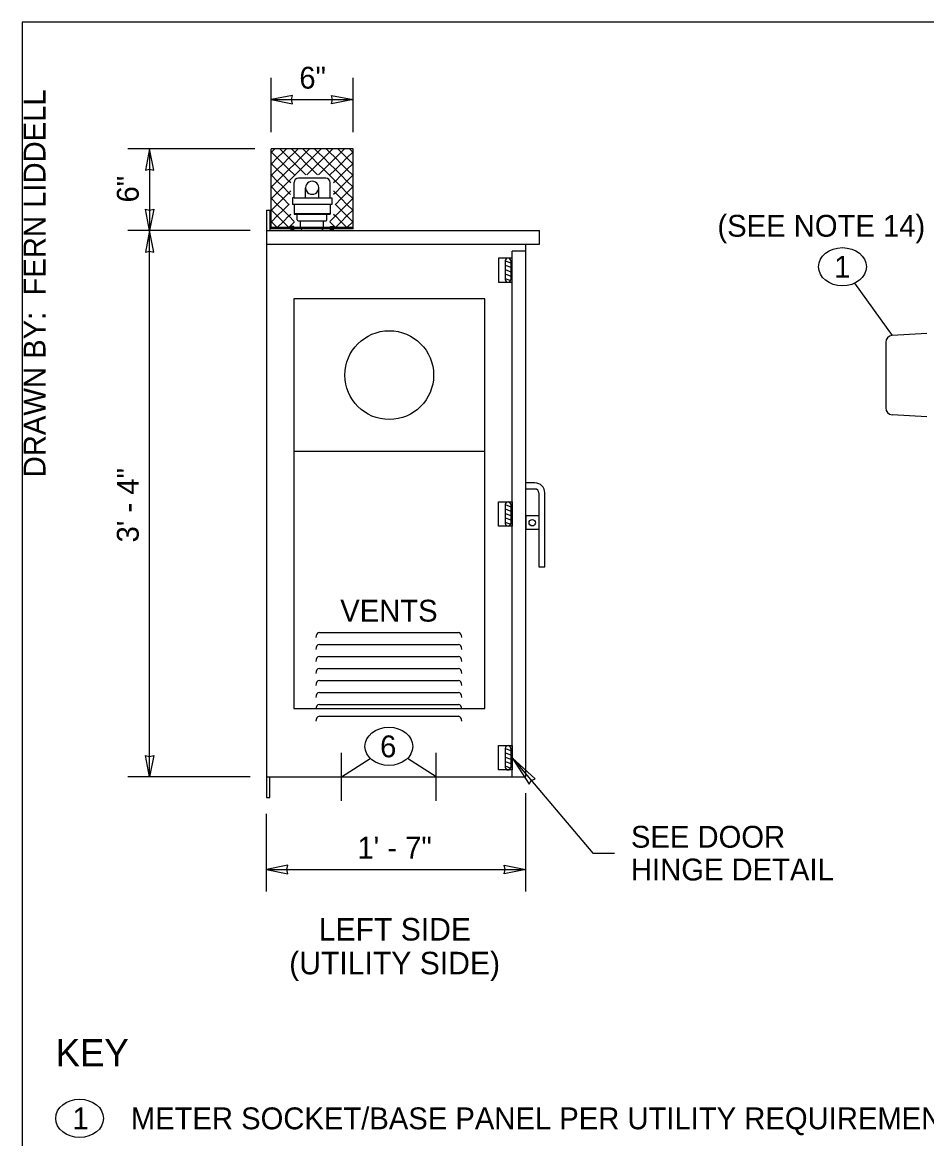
# Model space of a CAD drawing. Extents: x 99862 to 103680, y 99470 to 105076.
# Drawn here: x 99862 to 100524, y 101258 to 102076 of the extents above; entities that cross this region are included whole.
import ezdxf

# ---------------------------------------------------------------- set-up
doc = ezdxf.new("R2010")
doc.units = 0
for name, color, linetype in [('Level 1', 7, 'Continuous'), ('Level 11', 7, 'Continuous'), ('Level 15', 7, 'Continuous'), ('Level 20', 7, 'Continuous'), ('Level 3', 7, 'Continuous'), ('Level 40', 7, 'Continuous'), ('Level 62', 7, 'Continuous')]:
    doc.layers.add(name, color=color, linetype=linetype)

msp = doc.modelspace()

# ---------------------------------------------------------------- linework, layer by layer
at = {"layer": 'Level 1'}
for p, q in [((100044.28, 101925.19), (100044.28, 101982.94)), ((100104.28, 101982.94), (100044.28, 101982.94)), ((100044.28, 101980.71), (100044.5, 101980.49)), ((100044.5, 101980.49), (100044.28, 101980.27)), ((100044.5, 101980.49), (100046.95, 101982.94)), ((100048.75, 101976.24), (100044.5, 101980.49)), ((100053, 101980.49), (100048.75, 101976.24)), ((100050.55, 101982.94), (100053, 101980.49)), ((100055.46, 101982.94), (100053, 101980.49)), ((100053, 101980.49), (100057.26, 101976.24)), ((100057.26, 101976.24), (100061.51, 101980.49)), ((100061.51, 101980.49), (100059.06, 101982.94)), ((100063.97, 101982.94), (100061.51, 101980.49)), ((100061.51, 101980.49), (100065.77, 101976.24)), ((100065.77, 101976.24), (100070.02, 101980.49)), ((100070.02, 101980.49), (100067.57, 101982.94)), ((100072.47, 101982.94), (100070.02, 101980.49)), ((100070.02, 101980.49), (100074.28, 101976.24)), ((100074.28, 101976.24), (100078.53, 101980.49)), ((100078.53, 101980.49), (100076.08, 101982.94)), ((100080.98, 101982.94), (100078.53, 101980.49)), ((100078.53, 101980.49), (100082.78, 101976.24)), ((100082.78, 101976.24), (100087.04, 101980.49)), ((100087.04, 101980.49), (100084.59, 101982.94)), ((100089.49, 101982.94), (100087.04, 101980.49)), ((100087.04, 101980.49), (100091.29, 101976.24)), ((100091.29, 101976.24), (100095.55, 101980.49)), ((100093.09, 101982.94), (100095.55, 101980.49)), ((100095.55, 101980.49), (100098, 101982.94)), ((100095.55, 101980.49), (100099.8, 101976.24)), ((100099.8, 101976.24), (100104.05, 101980.49)), ((100104.05, 101980.49), (100101.6, 101982.94)), ((100104.28, 101980.71), (100104.05, 101980.49)), ((100104.05, 101980.49), (100104.28, 101980.27)), ((100104.28, 101925.19), (100104.28, 101982.95)), ((100044.28, 101972.21), (100044.5, 101971.98)), ((100044.5, 101971.98), (100044.28, 101971.76)), ((100044.5, 101971.98), (100048.75, 101976.24)), ((100048.75, 101967.73), (100044.5, 101971.98)), ((100048.75, 101976.24), (100053, 101971.98)), ((100053, 101971.98), (100048.75, 101967.73)), ((100057.26, 101976.24), (100053, 101971.98)), ((100053, 101971.98), (100057.26, 101967.73)), ((100061.51, 101971.98), (100057.26, 101976.24)), ((100057.26, 101967.73), (100061.51, 101971.98)), ((100065.77, 101976.24), (100061.51, 101971.98)), ((100061.51, 101971.98), (100065.77, 101967.73)), ((100070.02, 101971.98), (100065.77, 101976.24)), ((100065.77, 101967.73), (100070.02, 101971.98)), ((100074.28, 101976.24), (100070.02, 101971.98)), ((100070.02, 101971.98), (100074.28, 101967.73)), ((100078.53, 101971.98), (100074.28, 101976.24)), ((100074.28, 101967.73), (100078.53, 101971.98)), ((100082.78, 101976.24), (100078.53, 101971.98)), ((100078.53, 101971.98), (100082.78, 101967.73)), ((100087.04, 101971.98), (100082.78, 101976.24)), ((100082.78, 101967.73), (100087.04, 101971.98)), ((100091.29, 101976.24), (100087.04, 101971.98)), ((100087.04, 101971.98), (100091.29, 101967.73)), ((100095.55, 101971.98), (100091.29, 101976.24)), ((100091.29, 101967.73), (100095.55, 101971.98)), ((100099.8, 101976.24), (100095.55, 101971.98)), ((100095.55, 101971.98), (100099.8, 101967.73)), ((100104.05, 101971.98), (100099.8, 101976.24)), ((100099.8, 101967.73), (100104.05, 101971.98)), ((100104.28, 101972.2), (100104.05, 101971.98)), ((100104.05, 101971.98), (100104.28, 101971.76)), ((100044.28, 101963.7), (100044.5, 101963.48)), ((100044.5, 101963.48), (100044.28, 101963.25)), ((100044.5, 101963.48), (100048.75, 101967.73)), ((100048.75, 101959.22), (100044.5, 101963.48)), ((100048.75, 101967.73), (100053, 101963.48)), ((100053, 101963.48), (100048.75, 101959.22)), ((100057.26, 101967.73), (100053, 101963.48)), ((100053, 101963.48), (100057.26, 101959.22)), ((100061.51, 101963.48), (100057.26, 101967.73)), ((100057.26, 101959.22), (100061.51, 101963.48)), ((100065.77, 101967.73), (100061.51, 101963.48)), ((100061.51, 101963.48), (100061.73, 101963.26)), ((100069.64, 101963.86), (100065.77, 101967.73)), ((100074.28, 101967.73), (100070.4, 101963.86)), ((100078.15, 101963.86), (100074.28, 101967.73)), ((100082.78, 101967.73), (100078.91, 101963.86)), ((100087.04, 101963.48), (100082.78, 101967.73)), ((100086.82, 101963.26), (100087.04, 101963.48)), ((100091.29, 101967.73), (100087.04, 101963.48)), ((100087.04, 101963.48), (100091.29, 101959.22)), ((100095.55, 101963.48), (100091.29, 101967.73)), ((100091.29, 101959.22), (100095.55, 101963.48)), ((100099.8, 101967.73), (100095.55, 101963.48)), ((100095.55, 101963.48), (100099.8, 101959.22)), ((100104.05, 101963.48), (100099.8, 101967.73)), ((100099.8, 101959.22), (100104.05, 101963.48)), ((100104.28, 101963.7), (100104.05, 101963.48)), ((100104.05, 101963.48), (100104.28, 101963.26)), ((100044.28, 101955.19), (100044.5, 101954.97)), ((100044.5, 101954.97), (100044.28, 101954.75)), ((100044.5, 101954.97), (100048.75, 101959.22)), ((100048.75, 101950.71), (100044.5, 101954.97)), ((100048.75, 101959.22), (100053, 101954.97)), ((100053, 101954.97), (100048.75, 101950.71)), ((100057.26, 101959.22), (100053, 101954.97)), ((100053, 101954.97), (100057.26, 101950.71)), ((100058.63, 101957.85), (100057.26, 101959.22)), ((100061.04, 101947.01), (100061.04, 101958.24)), ((100084.3, 101961.45), (100064.25, 101961.45)), ((100069.46, 101947.01), (100069.46, 101954.39)), ((100079.09, 101947.01), (100079.09, 101954.39)), ((100087.51, 101947.01), (100087.51, 101958.24)), ((100091.29, 101959.22), (100089.92, 101957.85)), ((100095.55, 101954.97), (100091.29, 101959.22)), ((100091.29, 101950.71), (100095.55, 101954.97)), ((100099.8, 101959.22), (100095.55, 101954.97)), ((100095.55, 101954.97), (100099.8, 101950.71)), ((100104.05, 101954.97), (100099.8, 101959.22)), ((100099.8, 101950.71), (100104.05, 101954.97)), ((100104.28, 101955.19), (100104.05, 101954.97)), ((100104.05, 101954.97), (100104.28, 101954.75)), ((100044.28, 101946.68), (100044.5, 101946.46)), ((100044.5, 101946.46), (100044.28, 101946.24)), ((100044.5, 101946.46), (100048.75, 101950.71)), ((100048.75, 101942.2), (100044.5, 101946.46)), ((100048.75, 101950.71), (100053, 101946.46)), ((100053, 101946.46), (100048.75, 101942.2)), ((100057.26, 101950.71), (100053, 101946.46)), ((100053, 101946.46), (100057.26, 101942.2)), ((100057.26, 101950.71), (100058.63, 101952.09)), ((100058.56, 101949.42), (100057.26, 101950.71)), ((100061.04, 101947.01), (100059.84, 101947.01)), ((100059.84, 101947.01), (100059.84, 101942.2)), ((100061.04, 101947.01), (100087.51, 101947.01)), ((100087.51, 101947.01), (100088.71, 101947.01)), ((100088.71, 101947.01), (100088.71, 101942.2)), ((100089.92, 101952.09), (100091.29, 101950.71)), ((100091.29, 101950.71), (100090, 101949.42)), ((100095.55, 101946.46), (100091.29, 101950.71)), ((100091.29, 101942.2), (100095.55, 101946.46)), ((100099.8, 101950.71), (100095.55, 101946.46)), ((100095.55, 101946.46), (100099.8, 101942.2)), ((100104.05, 101946.46), (100099.8, 101950.71)), ((100099.8, 101942.2), (100104.05, 101946.46)), ((100104.28, 101946.68), (100104.05, 101946.46)), ((100104.05, 101946.46), (100104.28, 101946.24)), ((100044.28, 101938.17), (100044.5, 101937.95)), ((100044.5, 101937.95), (100044.28, 101937.73)), ((100044.5, 101937.95), (100048.75, 101942.2)), ((100048.75, 101933.7), (100044.5, 101937.95)), ((100048.75, 101942.2), (100053, 101937.95)), ((100053, 101937.95), (100048.75, 101933.7)), ((100057.26, 101942.2), (100053, 101937.95)), ((100053, 101937.95), (100057.26, 101933.7)), ((100057.26, 101942.2), (100057.43, 101942.38)), ((100057.43, 101942.03), (100057.26, 101942.2)), ((100088.71, 101942.2), (100059.84, 101942.2)), ((100061.04, 101942.2), (100061.04, 101934.98)), ((100087.51, 101942.2), (100087.51, 101934.98)), ((100091.12, 101942.38), (100091.29, 101942.2)), ((100091.29, 101942.2), (100091.12, 101942.03)), ((100095.55, 101937.95), (100091.29, 101942.2)), ((100091.29, 101933.7), (100095.55, 101937.95)), ((100099.8, 101942.2), (100095.55, 101937.95)), ((100095.55, 101937.95), (100099.8, 101933.7)), ((100104.05, 101937.95), (100099.8, 101942.2)), ((100099.8, 101933.7), (100104.05, 101937.95)), ((100104.28, 101938.17), (100104.05, 101937.95)), ((100104.05, 101937.95), (100104.28, 101937.73)), ((100044.28, 101929.66), (100044.5, 101929.44)), ((100044.5, 101929.44), (100048.75, 101933.7)), ((100048.75, 101933.7), (100053, 101929.44)), ((100057.26, 101933.7), (100053, 101929.44)), ((100057.26, 101933.7), (100058.63, 101935.07)), ((100061.22, 101929.73), (100057.26, 101933.7)), ((100061.04, 101935.58), (100087.51, 101935.58)), ((100061.04, 101934.98), (100087.51, 101934.98)), ((100063.45, 101930.77), (100063.45, 101934.98)), ((100064.05, 101930.16), (100084.5, 101930.16)), ((100065.85, 101925.35), (100065.85, 101930.16)), ((100082.7, 101925.35), (100082.7, 101930.16)), ((100085.1, 101930.77), (100085.1, 101934.98)), ((100091.29, 101933.7), (100087.33, 101929.73)), ((100089.92, 101935.07), (100091.29, 101933.7)), ((100095.55, 101929.44), (100091.29, 101933.7)), ((100099.8, 101933.7), (100095.55, 101929.44)), ((100104.05, 101929.44), (100099.8, 101933.7)), ((100104.28, 101929.66), (100104.05, 101929.44)), ((100044.5, 101929.44), (100044.28, 101929.22)), ((100104.28, 101925.19), (100044.28, 101925.19)), ((100044.28, 101924.15), (100044.28, 101925.09)), ((100104.28, 101925.09), (100044.28, 101925.09)), ((100104.28, 101924.15), (100044.28, 101924.15)), ((100048.75, 101925.19), (100044.5, 101929.44)), ((100053, 101929.44), (100048.75, 101925.19)), ((100053, 101929.44), (100057.26, 101925.19)), ((100057.26, 101925.19), (100061.4, 101929.33)), ((100068.26, 101922.94), (100080.29, 101922.94)), ((100087.15, 101929.33), (100091.29, 101925.19)), ((100091.29, 101925.19), (100095.55, 101929.44)), ((100095.55, 101929.44), (100099.8, 101925.19)), ((100099.8, 101925.19), (100104.05, 101929.44)), ((100104.05, 101929.44), (100104.28, 101929.22)), ((100104.28, 101924.15), (100104.28, 101925.09)), ((100215.78, 101900.87), (100215.78, 101887.1)), ((100215.78, 101900.87), (100219.78, 101899.33)), ((100215.78, 101897.66), (100219.78, 101896.11)), ((100219.78, 101900.87), (100219.78, 101887.1)), ((100220.78, 101885.1), (100220.78, 101902.87)), ((100215.78, 101894.44), (100219.78, 101892.9)), ((100215.78, 101891.23), (100219.78, 101889.68)), ((100215.78, 101888.01), (100219.68, 101886.5)), ((100494.46, 101841.13), (100494.46, 101793.13)), ((100524.46, 101847.59), (100499.17, 101846.12)), ((100524.46, 101786.66), (100499.17, 101788.14)), ((100200.78, 101761.31), (100060.77, 101761.31)), ((100237.51, 101738.17), (100230.78, 101738.17)), ((100237.51, 101733.73), (100230.78, 101733.73)), ((100240.33, 101730.92), (100240.33, 101676.86)), ((100244.76, 101676.86), (100244.76, 101730.92)), ((100215.78, 101722.33), (100215.78, 101708.56)), ((100215.78, 101722.33), (100219.78, 101720.79)), ((100215.78, 101719.11), (100219.78, 101717.57)), ((100219.78, 101722.33), (100219.78, 101708.56)), ((100220.78, 101724.33), (100220.78, 101706.56)), ((100215.78, 101715.9), (100219.78, 101714.36)), ((100215.78, 101712.68), (100219.78, 101711.14)), ((100215.78, 101709.47), (100219.68, 101707.96)), ((100240.33, 101714.07), (100230.78, 101714.07)), ((100230.78, 101714.07), (100230.78, 101704.07)), ((100240.33, 101704.07), (100230.78, 101704.07)), ((100240.33, 101676.86), (100244.76, 101676.86)), ((100220.78, 101545.79), (100220.78, 101528.02)), ((100215.78, 101543.79), (100215.78, 101530.02)), ((100215.78, 101543.79), (100219.78, 101542.24)), ((100215.78, 101540.57), (100219.78, 101539.03)), ((100215.78, 101537.36), (100219.78, 101535.81)), ((100219.78, 101543.79), (100219.78, 101530.02)), ((100215.78, 101534.14), (100219.78, 101532.6)), ((100215.78, 101530.93), (100219.68, 101529.42))]:
    msp.add_line(p, q, dxfattribs=at)
for points in [[(99862, 99999.5), (103151, 99999.5), (103151, 102075.5), (99862, 102075.5)], [(100060.77, 101572.94), (100200.78, 101572.94), (100200.78, 101872.94), (100060.77, 101872.94)]]:
    msp.add_lwpolyline(points, close=True, dxfattribs=at)
for points in [[(100220.78, 101902.87), (100210.78, 101902.87), (100210.78, 101885.1), (100220.78, 101885.1)], [(100220.78, 101706.56), (100210.78, 101706.56), (100210.78, 101724.33), (100220.78, 101724.33)], [(100220.78, 101528.02), (100210.78, 101528.02), (100210.78, 101545.79), (100220.78, 101545.79)]]:
    msp.add_lwpolyline(points, dxfattribs=at)
for centre, radius in [((100130.78, 101817.13), 32.5), ((100235.55, 101709.07), 2.37)]:
    msp.add_circle(centre, radius, dxfattribs=at)
for centre, radius, start, end in [((100064.25, 101958.24), 3.21, 90, 180), ((100074.28, 101954.39), 4.81, 359.99971, 180), ((100074.28, 101954.39), 4.81, 180, 0.00029), ((100084.3, 101958.24), 3.21, 0, 90), ((100064.05, 101930.77), 0.602, 180, 270), ((100084.5, 101930.77), 0.602, 270, 0), ((100068.26, 101925.35), 2.41, 180, 270), ((100080.29, 101925.35), 2.41, 270, 0), ((100217.78, 101900.87), 2, 90, 180), ((100217.78, 101900.87), 2, 0, 90), ((100217.78, 101887.1), 2, 180, 270), ((100217.78, 101887.1), 2, 270, 0), ((100499.46, 101841.13), 5, 93.3424, 180), ((100499.46, 101793.13), 5, 180, 266.6576), ((100237.51, 101730.92), 7.25, 0, 90), ((100237.51, 101730.92), 2.82, 0, 90), ((100217.78, 101722.33), 2, 90, 180), ((100217.78, 101722.33), 2, 0, 90), ((100217.78, 101708.56), 2, 180, 270), ((100217.78, 101708.56), 2, 270, 0), ((100217.78, 101543.79), 2, 90, 180), ((100217.78, 101543.79), 2, 0, 90), ((100217.78, 101530.02), 2, 180, 270), ((100217.78, 101530.02), 2, 270, 0)]:
    msp.add_arc(centre, radius, start, end, dxfattribs=at)
at = {"layer": 'Level 11'}
for p, q in [((100079.59, 101628.62), (100181.41, 101628.62)), ((100079.59, 101619.85), (100181.41, 101619.85)), ((100079.59, 101611.09), (100181.41, 101611.09)), ((100079.59, 101602.33), (100181.41, 101602.33)), ((100079.59, 101593.56), (100181.41, 101593.56)), ((100079.59, 101584.8), (100181.41, 101584.8)), ((100079.59, 101576.04), (100181.41, 101576.04)), ((100079.59, 101567.27), (100181.41, 101567.27))]:
    msp.add_line(p, q, dxfattribs=at)
for centre, start_param, end_param in [((100079.59, 101624.98), 0, 1.570796), ((100181.41, 101624.98), 4.712389, 6.283185), ((100079.59, 101616.22), 0, 1.570796), ((100181.41, 101616.22), 4.712389, 6.283185), ((100079.59, 101607.45), 0, 1.570796), ((100181.41, 101607.45), 4.712389, 6.283185), ((100079.59, 101598.69), 0, 1.570796), ((100181.41, 101598.69), 4.712389, 6.283185), ((100079.59, 101589.93), 0, 1.570796), ((100181.41, 101589.93), 4.712389, 6.283185), ((100079.59, 101581.16), 0, 1.570796), ((100181.41, 101581.16), 4.712389, 6.283185), ((100079.59, 101572.4), 0, 1.570796), ((100181.41, 101572.4), 4.712389, 6.283185), ((100079.59, 101563.63), 0, 1.570796), ((100181.41, 101563.63), 4.712389, 6.283185)]:
    msp.add_ellipse(centre, major_axis=(0, 3.64), ratio=0.707107, start_param=start_param, end_param=end_param, dxfattribs=at)
at = {"layer": 'Level 15'}
for p, q in [((100044.28, 101994.95), (100044.28, 102034.95)), ((100104.28, 101994.95), (100104.28, 102034.95)), ((100044.28, 102018.95), (100104.28, 102018.95)), ((100032.28, 101982.94), (99939.25, 101982.94)), ((99955.25, 101982.94), (99955.25, 101922.94)), ((100040.78, 101937.94), (100043.28, 101937.94)), ((100043.28, 101937.94), (100043.28, 101922.94)), ((100028.78, 101922.94), (99939.25, 101922.94)), ((99955.25, 101522.94), (99955.25, 101922.94)), ((100040.78, 101912.94), (100240.78, 101912.94)), ((100220.78, 101522.94), (100220.78, 101907.94)), ((100230.78, 101907.94), (100220.78, 101907.94)), ((100471.54, 101884.37), (100499.17, 101846.12)), ((100095.78, 101505.44), (100095.78, 101540.44)), ((100165.23, 101505.44), (100165.23, 101540.44)), ((100095.78, 101522.94), (100116.86, 101536.5)), ((100165.23, 101522.94), (100144.14, 101536.5)), ((100220.78, 101536.9), (100279.83, 101467.06)), ((100028.78, 101522.94), (99939.25, 101522.94)), ((100043.28, 101507.94), (100043.28, 101522.94)), ((100040.78, 101507.94), (100043.28, 101507.94)), ((100230.78, 101439.08), (100230.78, 101510.94)), ((100040.78, 101439.08), (100040.78, 101495.94)), ((100279.83, 101467.06), (100295.83, 101467.06)), ((100040.78, 101455.08), (100230.78, 101455.08))]:
    msp.add_line(p, q, dxfattribs=at)
for points in [[(100044.28, 102018.95), (100060, 102015.86), (100059.27, 102018.95), (100060, 102022.03)], [(100104.28, 102018.95), (100088.55, 102015.86), (100089.28, 102018.95), (100088.55, 102022.03)], [(99955.25, 101982.94), (99952.16, 101967.22), (99955.25, 101967.95), (99958.33, 101967.22)], [(99955.25, 101922.94), (99952.16, 101938.67), (99955.25, 101937.94), (99958.33, 101938.67)], [(99955.25, 101922.94), (99952.16, 101907.22), (99955.25, 101907.95), (99958.33, 101907.22)], [(99955.25, 101522.94), (99952.16, 101538.67), (99955.25, 101537.94), (99958.33, 101538.67)], [(100220.78, 101536.9), (100233.24, 101517.54), (100234.83, 101520.28), (100237.79, 101521.4)], [(100040.78, 101455.08), (100056.5, 101452), (100055.77, 101455.08), (100056.5, 101458.17)], [(100230.78, 101455.08), (100215.05, 101452), (100215.78, 101455.08), (100215.05, 101458.17)]]:
    msp.add_lwpolyline(points, close=True, dxfattribs=at)
at = {"layer": 'Level 20'}
for centre in [(100462.78, 101896.49), (100130.5, 101545.27), (99903.95, 101272.85)]:
    msp.add_ellipse(centre, major_axis=(-17.5, 0), ratio=0.8, dxfattribs=at)
at = {"layer": 'Level 40'}
for p, q in [((100040.78, 101937.94), (100040.78, 101507.94)), ((100040.78, 101922.94), (100240.78, 101922.94)), ((100240.78, 101912.94), (100240.78, 101922.94)), ((100230.78, 101522.94), (100230.78, 101912.94)), ((100040.78, 101522.94), (100230.78, 101522.94))]:
    msp.add_line(p, q, dxfattribs=at)
for points in [[(100061.18, 101923.19), (100061.18, 101922.94), (100058.49, 101922.94), (100058.49, 101923.19)], [(100061.15, 101923.35), (100061.15, 101923.19), (100058.52, 101923.19), (100058.52, 101923.35)], [(100060.82, 101925.11), (100060.82, 101925.88), (100058.85, 101925.88), (100058.85, 101925.11)], [(100060.82, 101923.35), (100060.82, 101924.15), (100058.85, 101924.15), (100058.85, 101923.35)], [(100087.37, 101923.19), (100087.37, 101922.94), (100090.06, 101922.94), (100090.06, 101923.19)], [(100087.4, 101923.35), (100087.4, 101923.19), (100090.03, 101923.19), (100090.03, 101923.35)], [(100087.73, 101925.11), (100087.73, 101925.88), (100089.7, 101925.88), (100089.7, 101925.11)], [(100087.73, 101923.35), (100087.73, 101924.15), (100089.7, 101924.15), (100089.7, 101923.35)]]:
    msp.add_lwpolyline(points, close=True, dxfattribs=at)

# ---------------------------------------------------------------- texts
at = {"layer": 'Level 20'}
for s, rotation, p in [('6"', 360, (100064.91, 102026.95)), ('6"', 90, (99947.25, 101943.58)), ('(SEE NOTE 14)', 360, (100371.19, 101918.48)), ('3\' - 4"', 90, (99947.25, 101694.61)), ('VENTS', 360, (100094.88, 101636.62)), ('1\' - 7"', 360, (100107.44, 101463.08)), ('METER SOCKET/BASE PANEL PER UTILITY REQUIREMENTS', 360, (99941.45, 101264.85))]:
    msp.add_text(s, height=16, rotation=rotation, dxfattribs=at).set_placement(p)
for s, height, p in [('1', 16, (100456.7, 101888.49)), ('6', 16, (100124.07, 101537.27)), ('SEE DOOR', 16, (100307.83, 101471.06)), ('HINGE DETAIL', 16, (100307.83, 101447.06)), ('LEFT SIDE', 16.5, (100079.12, 101403.07)), ('(UTILITY SIDE)', 16.5, (100057.49, 101378.32)), ('1', 16, (99898.67, 101264.85))]:
    msp.add_text(s, height=height, dxfattribs=at).set_placement(p)
at = {"layer": 'Level 3'}
msp.add_text('KEY', height=20, rotation=360, dxfattribs=at).set_placement((99886.45, 101310.85))
at = {"layer": 'Level 62'}
msp.add_text('DRAWN BY:  FERN LIDDELL', height=16, rotation=90, dxfattribs=at).set_placement((99879, 101742.3))

doc.saveas('drawing.dxf')
